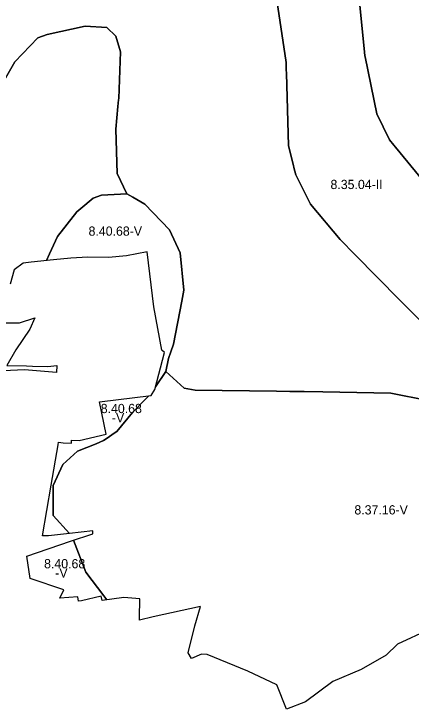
# Model space of a CAD drawing. Extents: x -547623 to -533936, y -1096714 to -1086523.
# Drawn here: x -545138 to -544707, y -1093867 to -1093114 of the extents above; entities that cross this region are included whole.
import ezdxf

# ---------------------------------------------------------------- set-up
doc = ezdxf.new("R2010")
doc.units = 0
doc.layers.add('Vrstva 27', color=7, linetype='Continuous')
doc.layers.add('Vrstva 28', color=7, linetype='Continuous')

msp = doc.modelspace()

# ---------------------------------------------------------------- linework, layer by layer
at = {"layer": 'Vrstva 28'}
for p, q in [((-544842.5, -1093166.5), (-544852.5, -1093099)), ((-544852.5, -1093099), (-544842.5, -1093166.5)), ((-544763, -1093100.5), (-544757.39, -1093155.19)), ((-544757.39, -1093155.19), (-544763, -1093100.5)), ((-545060.5, -1093127), (-545101.5, -1093136)), ((-545101.5, -1093136), (-545060.5, -1093127)), ((-545037, -1093128.5), (-545060.5, -1093127)), ((-545060.5, -1093127), (-545037, -1093128.5)), ((-545027, -1093138), (-545037, -1093128.5)), ((-545037, -1093128.5), (-545027, -1093138)), ((-545111.5, -1093139.5), (-545136.5, -1093165.5)), ((-545136.5, -1093165.5), (-545111.5, -1093139.5)), ((-545101.5, -1093136), (-545111.5, -1093139.5)), ((-545111.5, -1093139.5), (-545101.5, -1093136)), ((-545022, -1093155), (-545027, -1093138)), ((-545027, -1093138), (-545022, -1093155)), ((-545024, -1093205.5), (-545022, -1093155)), ((-545022, -1093155), (-545024, -1093205.5)), ((-544757.39, -1093155.19), (-544757, -1093159)), ((-544757, -1093159), (-544757.39, -1093155.19)), ((-544757, -1093159), (-544756.77, -1093160.09)), ((-544756.77, -1093160.09), (-544757, -1093159)), ((-544756.77, -1093160.09), (-544744, -1093222)), ((-544744, -1093222), (-544756.77, -1093160.09)), ((-545136.5, -1093165.5), (-545157, -1093201)), ((-545157, -1093201), (-545136.5, -1093165.5)), ((-544842.29, -1093174.21), (-544842.5, -1093166.5)), ((-544842.5, -1093166.5), (-544842.29, -1093174.21)), ((-544842.18, -1093177.99), (-544842.29, -1093174.21)), ((-544842.29, -1093174.21), (-544842.18, -1093177.99)), ((-544840, -1093256.5), (-544842.18, -1093177.99)), ((-544842.18, -1093177.99), (-544840, -1093256.5)), ((-545024.79, -1093214.18), (-545024.11, -1093206.75)), ((-545024.11, -1093206.75), (-545024.79, -1093214.18)), ((-545024.11, -1093206.75), (-545024, -1093205.5)), ((-545024, -1093205.5), (-545024.11, -1093206.75)), ((-545027, -1093238.5), (-545024.79, -1093214.18)), ((-545024.79, -1093214.18), (-545027, -1093238.5)), ((-544744, -1093222), (-544730.5, -1093250)), ((-544730.5, -1093250), (-544744, -1093222)), ((-545025.5, -1093286.5), (-545027, -1093238.5)), ((-545027, -1093238.5), (-545025.5, -1093286.5)), ((-544730.5, -1093250), (-544725.67, -1093255.87)), ((-544725.67, -1093255.87), (-544730.5, -1093250)), ((-544834.59, -1093277.82), (-544840, -1093256.5)), ((-544840, -1093256.5), (-544834.59, -1093277.82)), ((-544725.67, -1093255.87), (-544723.86, -1093258.07)), ((-544723.86, -1093258.07), (-544725.67, -1093255.87)), ((-544723.86, -1093258.07), (-544693.91, -1093294.48)), ((-544693.91, -1093294.48), (-544723.86, -1093258.07)), ((-544834.02, -1093280.04), (-544834.59, -1093277.82)), ((-544834.59, -1093277.82), (-544834.02, -1093280.04)), ((-544832, -1093288), (-544834.02, -1093280.04)), ((-544834.02, -1093280.04), (-544832, -1093288)), ((-545015, -1093308.5), (-545025.5, -1093286.5)), ((-545025.5, -1093286.5), (-545015, -1093308.5)), ((-544816, -1093320), (-544832, -1093288)), ((-544832, -1093288), (-544816, -1093320)), ((-545051.5, -1093313.5), (-545055.96, -1093317.1)), ((-545055.96, -1093317.1), (-545051.5, -1093313.5)), ((-545042.5, -1093310), (-545051.5, -1093313.5)), ((-545051.5, -1093313.5), (-545042.5, -1093310)), ((-545015, -1093308.5), (-545042.5, -1093310)), ((-545042.5, -1093310), (-545015, -1093308.5)), ((-545008.48, -1093312.35), (-545015, -1093308.5)), ((-545015, -1093308.5), (-545008.48, -1093312.35)), ((-545004.24, -1093314.84), (-545008.48, -1093312.35)), ((-545008.48, -1093312.35), (-545004.24, -1093314.84)), ((-545000, -1093317.35), (-545004.24, -1093314.84)), ((-545004.24, -1093314.84), (-545000, -1093317.35)), ((-545060.57, -1093320.81), (-545069.5, -1093328)), ((-545069.5, -1093328), (-545060.57, -1093320.81)), ((-545055.96, -1093317.1), (-545060.57, -1093320.81)), ((-545060.57, -1093320.81), (-545055.96, -1093317.1)), ((-544995.5, -1093320), (-545000, -1093317.35)), ((-545000, -1093317.35), (-544995.5, -1093320)), ((-544969, -1093347.5), (-544995.5, -1093320)), ((-544995.5, -1093320), (-544969, -1093347.5)), ((-544784, -1093358), (-544816, -1093320)), ((-544816, -1093320), (-544784, -1093358)), ((-545069.5, -1093328), (-545090.5, -1093355)), ((-545090.5, -1093355), (-545069.5, -1093328)), ((-544957.5, -1093372.5), (-544969, -1093347.5)), ((-544969, -1093347.5), (-544957.5, -1093372.5)), ((-545090.5, -1093355), (-545099.08, -1093373.77)), ((-545099.08, -1093373.77), (-545090.5, -1093355)), ((-544767.47, -1093374.72), (-544784, -1093358)), ((-544784, -1093358), (-544767.47, -1093374.72)), ((-545099.08, -1093373.77), (-545102.31, -1093380.86)), ((-545102.31, -1093380.86), (-545099.08, -1093373.77)), ((-544953.5, -1093413), (-544957.5, -1093372.5)), ((-544957.5, -1093372.5), (-544953.5, -1093413)), ((-544719.39, -1093423.35), (-544767.47, -1093374.72)), ((-544767.47, -1093374.72), (-544719.39, -1093423.35)), ((-545102.31, -1093380.86), (-545102.31, -1093380.86)), ((-545102.31, -1093380.86), (-545102.31, -1093380.86)), ((-544955.71, -1093424.75), (-544953.5, -1093413)), ((-544953.5, -1093413), (-544955.71, -1093424.75)), ((-544964.5, -1093471.5), (-544955.71, -1093424.75)), ((-544955.71, -1093424.75), (-544964.5, -1093471.5)), ((-544697, -1093446), (-544719.39, -1093423.35)), ((-544719.39, -1093423.35), (-544697, -1093446)), ((-544967.5, -1093479.97), (-544964.5, -1093471.5)), ((-544964.5, -1093471.5), (-544967.5, -1093479.97)), ((-544970, -1093487), (-544967.5, -1093479.97)), ((-544967.5, -1093479.97), (-544970, -1093487)), ((-544973, -1093501), (-544970, -1093487)), ((-544970, -1093487), (-544973, -1093501)), ((-545098.33, -1093501.61), (-545098.33, -1093501.61)), ((-544983.99, -1093517.86), (-544973, -1093501)), ((-544973, -1093501), (-544983.99, -1093517.86)), ((-544953, -1093519), (-544973, -1093501)), ((-544973, -1093501), (-544953, -1093519)), ((-544941, -1093521.5), (-544953, -1093519)), ((-544953, -1093519), (-544941, -1093521.5)), ((-544852.98, -1093522.45), (-544941, -1093521.5)), ((-544941, -1093521.5), (-544852.98, -1093522.45)), ((-544838.6, -1093522.61), (-544852.98, -1093522.45)), ((-544852.98, -1093522.45), (-544838.6, -1093522.61)), ((-544823.02, -1093522.78), (-544838.6, -1093522.61)), ((-544838.6, -1093522.61), (-544823.02, -1093522.78)), ((-544802.5, -1093523), (-544823.02, -1093522.78)), ((-544823.02, -1093522.78), (-544802.5, -1093523)), ((-544729, -1093524.5), (-544802.5, -1093523)), ((-544802.5, -1093523), (-544729, -1093524.5)), ((-544672.58, -1093535.73), (-544729, -1093524.5)), ((-544729, -1093524.5), (-544672.58, -1093535.73)), ((-545000, -1093536.29), (-544991.43, -1093527.51)), ((-544991.43, -1093527.51), (-545000, -1093536.29)), ((-545008.87, -1093545.37), (-545003.56, -1093539.93)), ((-545003.56, -1093539.93), (-545008.87, -1093545.37)), ((-545003.56, -1093539.93), (-545000, -1093536.29)), ((-545000, -1093536.29), (-545003.56, -1093539.93)), ((-545026, -1093566), (-545008.87, -1093545.37)), ((-545008.87, -1093545.37), (-545026, -1093566)), ((-545036.38, -1093573.16), (-545028.8, -1093567.93)), ((-545028.8, -1093567.93), (-545036.38, -1093573.16)), ((-545028.8, -1093567.93), (-545026, -1093566)), ((-545026, -1093566), (-545028.8, -1093567.93)), ((-545048.56, -1093579.31), (-545040.5, -1093576)), ((-545040.5, -1093576), (-545048.56, -1093579.31)), ((-545040.5, -1093576), (-545036.38, -1093573.16)), ((-545036.38, -1093573.16), (-545040.5, -1093576)), ((-545068.5, -1093587.5), (-545048.56, -1093579.31)), ((-545048.56, -1093579.31), (-545068.5, -1093587.5)), ((-545084.5, -1093602), (-545068.5, -1093587.5)), ((-545068.5, -1093587.5), (-545084.5, -1093602)), ((-545095, -1093624.5), (-545084.5, -1093602)), ((-545084.5, -1093602), (-545095, -1093624.5)), ((-545095, -1093657), (-545095, -1093624.5)), ((-545095, -1093624.5), (-545095, -1093657)), ((-545077.49, -1093676.65), (-545095, -1093657)), ((-545095, -1093657), (-545077.49, -1093676.65)), ((-545077.49, -1093676.65), (-545077.49, -1093676.65)), ((-545077.49, -1093676.65), (-545077.49, -1093676.65)), ((-545059.5, -1093718.5), (-545072.97, -1093683.92)), ((-545072.97, -1093683.92), (-545059.5, -1093718.5)), ((-545040.12, -1093743.94), (-545059.5, -1093718.5)), ((-545059.5, -1093718.5), (-545040.12, -1093743.94)), ((-545036.73, -1093748.4), (-545040.12, -1093743.94)), ((-545040.12, -1093743.94), (-545036.73, -1093748.4)), ((-545036.73, -1093748.4), (-545036.73, -1093748.4)), ((-545036.73, -1093748.4), (-545036.73, -1093748.4))]:
    msp.add_line(p, q, dxfattribs=at)
for points in [[(-544922.5, -1092817.28), (-544880.5, -1092923.5), (-544878.05, -1092954.41), (-544878, -1092955), (-544880, -1092995.5), (-544879.39, -1093000), (-544875.5, -1093029), (-544865.83, -1093054.92), (-544864.42, -1093058.69), (-544863.33, -1093061.61), (-544863, -1093062.5), (-544852.5, -1093099), (-544842.5, -1093166.5), (-544842.29, -1093174.21), (-544842.18, -1093177.99), (-544840, -1093256.5), (-544834.59, -1093277.82), (-544834.02, -1093280.04), (-544832, -1093288), (-544816, -1093320), (-544784, -1093358), (-544767.47, -1093374.72), (-544719.39, -1093423.35), (-544697, -1093446)], [(-544693.91, -1093294.48), (-544723.86, -1093258.07), (-544725.67, -1093255.87), (-544730.5, -1093250), (-544744, -1093222), (-544756.77, -1093160.09), (-544757, -1093159), (-544757.39, -1093155.19), (-544763, -1093100.5)], [(-545102.31, -1093380.86), (-545102.31, -1093380.86), (-545099.08, -1093373.77), (-545090.5, -1093355), (-545069.5, -1093328), (-545060.57, -1093320.81), (-545055.96, -1093317.1), (-545051.5, -1093313.5), (-545042.5, -1093310), (-545015, -1093308.5), (-545025.5, -1093286.5), (-545027, -1093238.5), (-545024.79, -1093214.18), (-545024.11, -1093206.75), (-545024, -1093205.5), (-545022, -1093155), (-545027, -1093138), (-545037, -1093128.5), (-545060.5, -1093127), (-545101.5, -1093136), (-545111.5, -1093139.5), (-545136.5, -1093165.5), (-545157, -1093201)], [(-544687.52, -1093780.56), (-544721.65, -1093796.65), (-544734.01, -1093808.55), (-544761.13, -1093823.83), (-544791.86, -1093836.99), (-544821.6, -1093859.07), (-544842.21, -1093866.81), (-544852.46, -1093840.46), (-544883.81, -1093825.65), (-544927.99, -1093807.82), (-544934.39, -1093807.32), (-544945, -1093811.91), (-544948.57, -1093805.98), (-544941.42, -1093776.74), (-544935.17, -1093755.64), (-544986.73, -1093766.95), (-545001.58, -1093770.39), (-545001.54, -1093767.97), (-545001.21, -1093747.47), (-545018.46, -1093745.83), (-545042.07, -1093749.15), (-545042.84, -1093744.38), (-545064.39, -1093749.48), (-545067.55, -1093749.74), (-545068.24, -1093745.38), (-545087.94, -1093746.7), (-545083.53, -1093737.63), (-545120.06, -1093725.2), (-545123.52, -1093701), (-545076.28, -1093685), (-545051.9, -1093677.05), (-545052.17, -1093673.83), (-545077.24, -1093676.62), (-545100.06, -1093679.2), (-545106.44, -1093679.07), (-545097.16, -1093624.22), (-545089.74, -1093580.73), (-545089.1, -1093577.8), (-545084.06, -1093578.5), (-545075.25, -1093578.72), (-545075.1, -1093575.43), (-545066.98, -1093575.84), (-545037.64, -1093568.95), (-545044.84, -1093533.99), (-544988.92, -1093527.21), (-544984.75, -1093520.77), (-544974.26, -1093480.39), (-544977.34, -1093477.95), (-544985.95, -1093430.96), (-544993.25, -1093371.54), (-545015.69, -1093375.77), (-545035.12, -1093377.66), (-545057.58, -1093377.2), (-545075.86, -1093378.51), (-545094.82, -1093380.09), (-545118.95, -1093382.58), (-545127.54, -1093383.71), (-545137.32, -1093390.95), (-545141.73, -1093406.38)], [(-545147.44, -1093448.25), (-545131.6, -1093448.28), (-545114.85, -1093442.83), (-545120.23, -1093455.38), (-545135.36, -1093477.57), (-545145.3, -1093494.44), (-545124.01, -1093494.97), (-545117.31, -1093495.37), (-545100.88, -1093495.76), (-545091.11, -1093494.7), (-545091.45, -1093502.22), (-545126.09, -1093499.13), (-545164.4, -1093501)], [(-545072.97, -1093683.92), (-545072.97, -1093683.92)], [(-545072.97, -1093683.92), (-545059.5, -1093718.5), (-545040.12, -1093743.94), (-545036.73, -1093748.4)]]:
    msp.add_lwpolyline(points, dxfattribs=at)

# ---------------------------------------------------------------- texts
at = {"layer": 'Vrstva 27'}
for s, p in [('8.35.04-II', (-544794.37, -1093303.49)), ('8.40.68-V', (-545056.65, -1093354.03)), ('8.40.68', (-545043.46, -1093546.18)), ('-V', (-545031.33, -1093556.18)), ('8.37.16-V', (-544768.46, -1093655.98)), ('8.40.68', (-545104.87, -1093714.31)), ('-V', (-545092.74, -1093724.31))]:
    msp.add_text(s, height=10, dxfattribs=at).set_placement(p)

doc.saveas('drawing.dxf')
